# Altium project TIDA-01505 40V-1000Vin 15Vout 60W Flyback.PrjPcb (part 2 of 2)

## Sheet Flyback_PSR.SchDoc: Flyback_without_opto
size 431 x 279 mm; Date: Not shown in title block; ApprovedBy: Not shown in title block; CheckedBy: Not shown in title block; Author: Not shown in title block; CompanyName: Not shown in title block; DrawnBy: X.Gong; Engineer: Not shown in title block; Organization: Not shown in title block; Address1: Not shown in title block; Address2: Not shown in title block; Address3: Not shown in title block; Address4: Not shown in title block; DocumentNumber: 1; Revision: Use project parameter SCH_Rev; SheetNumber: 2; SheetTotal: 4; PageSetup: Record=PageOptions¦CenterHorizontal=True¦CenterVertical=True¦PrintScale=1.00¦XCorrection=1.00¦YCorrection=1.00¦PrintKind=0¦BorderSize=5000000¦LeftOffset=0¦BottomOffset=0¦Orientation=2¦PaperLength=1000¦PaperWidth=1000¦Scale=100¦PaperSource=15¦PrintQuality=600¦MediaType=1¦DitherType=10¦PaperKind=Letter¦PrintScaleMode=1
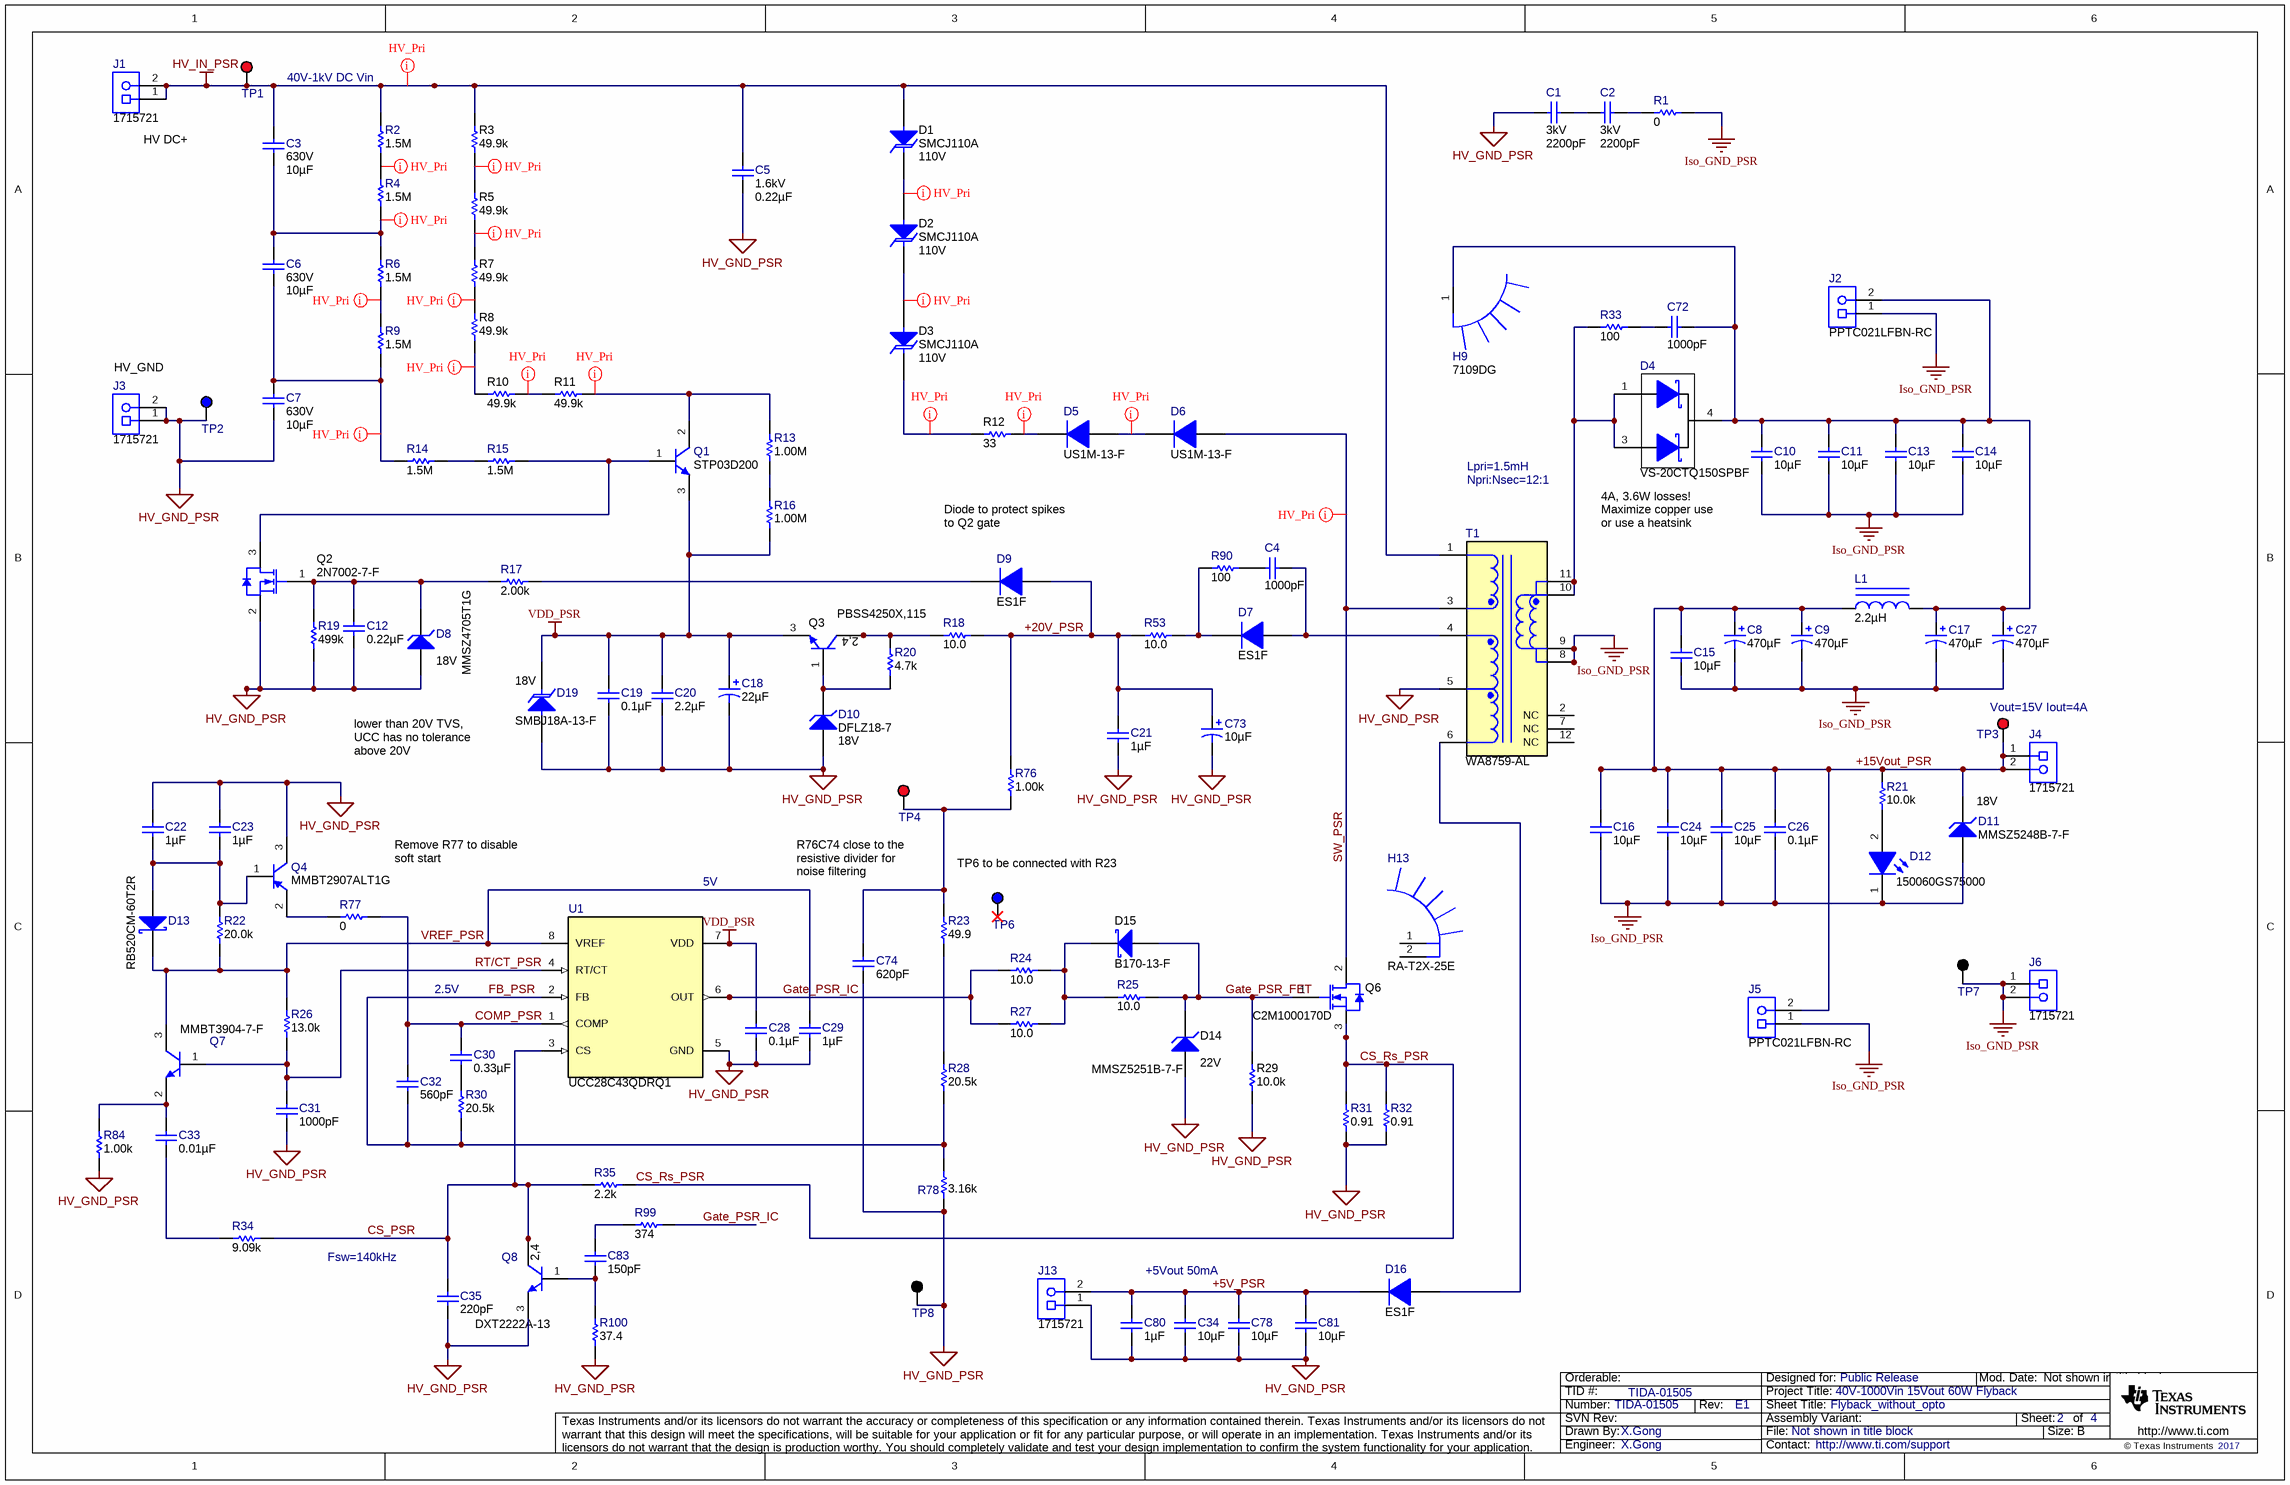
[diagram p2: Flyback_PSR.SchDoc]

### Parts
C1  VDC_V: 3kV  ValueDisplayed: 2200pF  [CK45-RR_1650x600]  (hidden comment: CK45-R3FD222K-NRA)
C2  VDC_V: 3kV  ValueDisplayed: 2200pF  [CK45-RR_1650x600]  (hidden comment: CK45-R3FD222K-NRA)
C3  VDC_V: 630V  ValueDisplayed: 10µF  [B32776P_4200x1800x3250]  (hidden comment: B32776P6106K000)
C4  ValueDisplayed: 1000pF  [1206]  (hidden comment: GRM31B5C2J102JW01L)
C5  VDC_V: 1.6kV  ValueDisplayed: 0.22µF  [Kemet_3200x1800x3300]  (hidden comment: R76TR32204030J)
C6  VDC_V: 630V  ValueDisplayed: 10µF  [B32776P_4200x1800x3250]  (hidden comment: B32776P6106K000)
C7  VDC_V: 630V  ValueDisplayed: 10µF  [B32776P_4200x1800x3250]  (hidden comment: B32776P6106K000)
C8  ValueDisplayed: 470µF  [Chemi-Con_1000x2000]  (hidden comment: EKZE350ELL471MJ20S)
C9  ValueDisplayed: 470µF  [Chemi-Con_1000x2000]  (hidden comment: EKZE350ELL471MJ20S)
C10  ValueDisplayed: 10µF  [0805_HV]  (hidden comment: GRM21BR6YA106KE43L)
C11  ValueDisplayed: 10µF  [0805_HV]  (hidden comment: GRM21BR6YA106KE43L)
C12  ValueDisplayed: 0.22µF  [0805_HV]  (hidden comment: GRM21BR71H224KA01L)
C13  ValueDisplayed: 10µF  [0805_HV]  (hidden comment: GRM21BR6YA106KE43L)
C14  ValueDisplayed: 10µF  [0805_HV]  (hidden comment: GRM21BR6YA106KE43L)
C15  ValueDisplayed: 10µF  [0805_HV]  (hidden comment: GRM21BR6YA106KE43L)
C16  ValueDisplayed: 10µF  [0805_HV]  (hidden comment: GRM21BR6YA106KE43L)
C17  ValueDisplayed: 470µF  [Chemi-Con_1000x2000]  (hidden comment: EKZE350ELL471MJ20S)
C18  ValueDisplayed: 22µF  [SM_RADIAL_D]  (hidden comment: EEE-FK1H220P)
C19  ValueDisplayed: 0.1µF  [0805_HV]  (hidden comment: C2012X7R1H104K085AA)
C20  ValueDisplayed: 2.2µF  [0805_HV]  (hidden comment: CGA4J3X7R1H225K125AB)
C21  ValueDisplayed: 1µF  [1206_180]  (hidden comment: GRM31CR72A105KA01L)
C22  ValueDisplayed: 1µF  [0805_HV]  (hidden comment: GRM21BR71E105KA99L)
C23  ValueDisplayed: 1µF  [0805_HV]  (hidden comment: GRM21BR71E105KA99L)
C24  ValueDisplayed: 10µF  [0805_HV]  (hidden comment: GRM21BR6YA106KE43L)
C25  ValueDisplayed: 10µF  [0805_HV]  (hidden comment: GRM21BR6YA106KE43L)
C26  ValueDisplayed: 0.1µF  [0805_HV]  (hidden comment: C2012X7R1H104K085AA)
C27  ValueDisplayed: 470µF  [Chemi-Con_1000x2000]  (hidden comment: EKZE350ELL471MJ20S)
C28  ValueDisplayed: 0.1µF  [0805_HV]  (hidden comment: C2012X7R1H104K085AA)
C29  ValueDisplayed: 1µF  [0603]  (hidden comment: GRM188R71E105KA12D)
C30  ValueDisplayed: 0.33µF  [0805_HV]  (hidden comment: GRM21BR71E334KA01L)
C31  ValueDisplayed: 1000pF  [0805_HV]  (hidden comment: GCM2165C1H102JA16D)
C32  ValueDisplayed: 560pF  [0805_HV]  (hidden comment: GRM216R71E561KA01D)
C33  ValueDisplayed: 0.01µF  [0805_HV]  (hidden comment: GRM216R71H103KA01D)
C34  ValueDisplayed: 10µF  [0805_HV]  (hidden comment: GRM21BR6YA106KE43L)
C35  ValueDisplayed: 220pF  [0805_HV]  (hidden comment: GRM2165C1H221JA01D)
C72  ValueDisplayed: 1000pF  [1206]  (hidden comment: GRM31B5C2J102JW01L)
C73  ValueDisplayed: 10µF  [SM_RADIAL_E]  (hidden comment: EEE-2AA100UP)
C74  ValueDisplayed: 620pF  [0805_HV]  (hidden comment: GRM2165C2A621JA01D)
C78  ValueDisplayed: 10µF  [0805_HV]  (hidden comment: GRM21BR6YA106KE43L)
C80  ValueDisplayed: 1µF  [1206_180]  (hidden comment: GRM31CR72A105KA01L)
C81  ValueDisplayed: 10µF  [0805_HV]  (hidden comment: GRM21BR6YA106KE43L)
C83  ValueDisplayed: 150pF  [0805_HV]  (hidden comment: GRM2165C1H151JA01D)
D1  SMCJ110A  value 110V  [SMC_265]
D2  SMCJ110A  value 110V  [SMC_265]
D3  SMCJ110A  value 110V  [SMC_265]
D4  VS-20CTQ150SPBF  [DDPAK]
D5  US1M-13-F  [SMA]
D6  US1M-13-F  [SMA]
D7  ES1F  [SMA]
D8  MMSZ4705T1G  value 18V  [SOD-123]
D9  ES1F  [SMA]
D10  DFLZ18-7  value 18V  [PowerDI123]
D11  MMSZ5248B-7-F  value 18V  [SOD-123]
D12  150060GS75000  [WL-SMCW_GREEN]
D13  RB520CM-60T2R  [SOD-923]
D14  MMSZ5251B-7-F  value 22V  [SOD-123]
D15  B170-13-F  [SMA]
D16  ES1F  [SMA]
D19  SMBJ18A-13-F  Vr_V: 18V  [SMB]
H9  7109DG  [Aavid_7109DG]
H13  RA-T2X-25E  [HSINK_RA-T2X-25E]
J1  1715721  [PhoenixContact_1715721]
J2  PPTC021LFBN-RC  [CONN_PPTC021LFBN-RC]
J3  1715721  [PhoenixContact_1715721]
J4  1715721  [PhoenixContact_1715721]
J5  PPTC021LFBN-RC  [CONN_PPTC021LFBN-RC]
J6  1715721  [PhoenixContact_1715721]
J13  1715721  [PhoenixContact_1715721]
L1  ValueDisplayed: 2.2µH  [XAL6030]  (hidden comment: XAL6030-222MEB)
Q1  STP03D200  [TO-220AB]
Q2  2N7002-7-F  [SOT-23]
Q3  PBSS4250X,115  [SOT-89-3]
Q4  MMBT2907ALT1G  [SOT-23]
Q6  C2M1000170D  [TO-247]
Q7  MMBT3904-7-F  [SOT-23]
Q8  DXT2222A-13  [SOT-89-3]
R1  ValueDisplayed: 0  [2010]  (hidden comment: CRCW20100000Z0EF)
R2  ValueDisplayed: 1.5M  [2010]  (hidden comment: ERJ12ZYJ155U)
R3  ValueDisplayed: 49.9k  [2010]  (hidden comment: CRCW201049K9FKEF)
R4  ValueDisplayed: 1.5M  [2010]  (hidden comment: ERJ12ZYJ155U)
R5  ValueDisplayed: 49.9k  [2010]  (hidden comment: CRCW201049K9FKEF)
R6  ValueDisplayed: 1.5M  [2010]  (hidden comment: ERJ12ZYJ155U)
R7  ValueDisplayed: 49.9k  [2010]  (hidden comment: CRCW201049K9FKEF)
R8  ValueDisplayed: 49.9k  [2010]  (hidden comment: CRCW201049K9FKEF)
R9  ValueDisplayed: 1.5M  [2010]  (hidden comment: ERJ12ZYJ155U)
R10  ValueDisplayed: 49.9k  [2010]  (hidden comment: CRCW201049K9FKEF)
R11  ValueDisplayed: 49.9k  [2010]  (hidden comment: CRCW201049K9FKEF)
R12  ValueDisplayed: 33  [2010]  (hidden comment: CRCW201033R0JNEF)
R13  ValueDisplayed: 1.00M  [2010]  (hidden comment: CRCW20101M00FKEF)
R14  ValueDisplayed: 1.5M  [2010]  (hidden comment: ERJ12ZYJ155U)
R15  ValueDisplayed: 1.5M  [2010]  (hidden comment: ERJ12ZYJ155U)
R16  ValueDisplayed: 1.00M  [2010]  (hidden comment: CRCW20101M00FKEF)
R17  ValueDisplayed: 2.00k  [0805_HV]  (hidden comment: CRCW08052K00FKEA)
R18  ValueDisplayed: 10.0  [0805_HV]  (hidden comment: CRCW080510R0FKEA)
R19  ValueDisplayed: 499k  [0603]  (hidden comment: CRCW0603499KFKEA)
R20  ValueDisplayed: 4.7k  [0603]  (hidden comment: CRCW06034K70JNEA)
R21  ValueDisplayed: 10.0k  [0603]  (hidden comment: CRCW060310K0FKEA)
R22  ValueDisplayed: 20.0k  [0805_HV]  (hidden comment: CRCW080520K0FKEA)
R23  ValueDisplayed: 49.9  [0805_HV]  (hidden comment: CRCW080549R9FKEA)
R24  ValueDisplayed: 10.0  [1206]  (hidden comment: CRCW120610R0FKEA)
R25  ValueDisplayed: 10.0  [1206]  (hidden comment: CRCW120610R0FKEA)
R26  ValueDisplayed: 13.0k  [0805_HV]  (hidden comment: CRCW080513K0FKEA)
R27  ValueDisplayed: 10.0  [1206]  (hidden comment: CRCW120610R0FKEA)
R28  ValueDisplayed: 20.5k  [0805_HV]  (hidden comment: CRCW080520K5FKEA)
R29  ValueDisplayed: 10.0k  [1206]  (hidden comment: CRCW120610K0FKEA)
R30  ValueDisplayed: 20.5k  [0805_HV]  (hidden comment: CRCW080520K5FKEA)
R31  ValueDisplayed: 0.91  [2010]  (hidden comment: CRM2010-FX-R910ELF)
R32  ValueDisplayed: 0.91  [2010]  (hidden comment: CRM2010-FX-R910ELF)
R33  ValueDisplayed: 100  [1206]  (hidden comment: CRCW1206100RFKEA)
R34  ValueDisplayed: 9.09k  [0805_HV]  (hidden comment: CRCW08059K09FKEA)
R35  ValueDisplayed: 2.2k  [0805_HV]  (hidden comment: CRCW08052K20JNEA)
R53  ValueDisplayed: 10.0  [1206]  (hidden comment: CRCW120610R0FKEA)
R76  ValueDisplayed: 1.00k  [0805_HV]  (hidden comment: CRCW08051K00FKEA)
R77  ValueDisplayed: 0  [0805_HV]  (hidden comment: CRCW08050000Z0EA)
R78  ValueDisplayed: 3.16k  [0805_HV]  (hidden comment: CRCW08053K16FKEA)
R84  ValueDisplayed: 1.00k  [0805_HV]  (hidden comment: CRCW08051K00FKEA)
R90  ValueDisplayed: 100  [1206]  (hidden comment: CRCW1206100RFKEA)
R99  ValueDisplayed: 374  [0805_HV]  (hidden comment: CRCW0805374RFKEA)
R100  ValueDisplayed: 37.4  [0805_HV]  (hidden comment: CRCW080537R4FKEA)
T1  WA8759-AL  [Coilcraft_WA8537-BL]
TP1  5005  [Keystone5005]  (value not drawn)
TP2  5122  [Keystone5122]  (value not drawn)
TP3  5005  [Keystone5005]  (value not drawn)
TP4  5005  [Keystone5005]  (value not drawn)
TP6  5122  [Keystone5122]  (value not drawn)
TP7  5006  [Keystone5006]  (value not drawn)
TP8  5006  [Keystone5006]  (value not drawn)
U1  UCC28C43QDRQ1  [D0008A_N]

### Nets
HV_GND_PSR: C1.2 C5.2 C7.2 C12.2 C18.2(-) C19.2 C20.2 C21.2 C22.1 C23.1 C28.2 C29.2 C31.2 C34.2 C35.2 C73.2(-) C74.2 C78.2 C80.2 C81.2 D8.2(A) D10.2(A) D14.2(A) D19.2(A) J3.1 J3.2 J13.1 Q2.2(S) Q4.3(C) Q8.3(E) R19.1 R29.1 R31.1 R32.1 R78.1 R84.1 R100.1 T1.5 TP2.1 TP8.1 U1.5(GND)
HV_IN_PSR: C3.1 C5.1 D1.2(A) J1.1 J1.2 R2.2 R3.2 T1.1 TP1.1
Iso_GND_PSR: C8.2(-) C9.2(-) C10.2 C11.2 C13.2 C14.2 C15.2 C16.2 C17.2(-) C24.2 C25.2 C26.2 C27.2(-) D11.2(A) D12.1(K) J2.1 J5.1 J6.1 J6.2 R1.2 T1.8 T1.9 TP7.1
VDD_PSR: C18.1(+) C19.1 C20.1 C28.1 D19.1(K) Q1.3(E) Q3.3(E) R16.1 U1.7(VDD)
+5V_PSR: C34.1 C78.1 C80.1 C81.1 D16.1(K) J13.2
+15Vout_PSR: C8.1(+) C9.1(+) C15.1 C16.1 C24.1 C25.1 C26.1 D11.1(K) J4.1 J4.2 J5.2 L1.1 R21.2 TP3.1
+20V_PSR: C21.1 C73.1(+) D9.2(A) R18.2 R53.1 R76.2
COMP_PSR: C30.1 C32.1 R77.2 U1.1(COMP)
CS_PSR: C35.1 Q8.2(C) Q8.4(C) R34.2 R35.1 U1.3(CS)
CS_Rs_PSR: Q6.3(S) R31.2 R32.2 R35.2
FB_PSR: C32.2 R28.1 R30.1 R78.2 U1.2(FB)
Gate_PSR_FET: D14.1(K) D15.2(A) Q6.1(G) R25.2 R29.2
Gate_PSR_IC: R24.1 R27.1 R99.1 U1.6(OUT)
RT/CT_PSR: C31.1 Q7.1(B) R26.1 U1.4(RT/CT)
SW_PSR: D6.2(A) Q6.2(D) T1.3
VREF_PSR: C29.1 D13.1(K) Q7.3(C) R22.1 R26.2 U1.8(VREF)
NetC1_1: C1.1 C2.2
NetC2_1: C2.1 R1.1
NetC3_2: C3.2 C6.1 R4.1 R6.2
NetC4_1: C4.1 D7.2(A) T1.4
NetC4_2: C4.2 R90.2
NetC6_2: C6.2 C7.1 R9.1 R14.2
NetC10_1: C10.1 C11.1 C13.1 C14.1 C17.1(+) C27.1(+) C72.1 D4.4(K) H9.1 J2.2 L1.2
NetC12_1: C12.1 D8.1(K) Q2.1(G) R17.1 R19.2
NetC22_2: C22.2 C23.2 D13.2(A) Q4.1(B) R22.2
NetC30_2: C30.2 R30.2
NetC33_1: C33.1 Q7.2(E) R84.2
NetC33_2: C33.2 R34.1
NetC72_2: C72.2 R33.2
NetC74_1: C74.1 R23.2 R76.1 TP4.1
NetC83_1: C83.1 R99.2
NetC83_2: C83.2 Q8.1(B) R100.2
NetD1_1: D1.1(K) D2.2(A)
NetD2_1: D2.1(K) D3.2(A)
NetD3_1: D3.1(K) R12.1
NetD4_1: D4.1(A) D4.3(A) R33.1 T1.10 T1.11
NetD5_1: D5.1(K) R12.2
NetD5_2: D5.2(A) D6.1(K)
NetD7_1: D7.1(K) R53.2 R90.1
NetD9_1: D9.1(K) R17.2
NetD10_1: D10.1(K) Q3.1(B) R20.1
NetD12_2: D12.2(A) R21.1
NetD15_1: D15.1(K) R24.2 R25.1 R27.2
NetD16_2: D16.2(A) T1.6
NetQ1_1: Q1.1(B) Q2.3(D) R15.1
NetQ1_2: Q1.2(C) R11.1 R13.2
NetQ3_2: Q3.2(C) Q3.4(C) R18.1 R20.2
NetQ4_2: Q4.2(E) R77.1
NetR2_1: R2.1 R4.2
NetR3_1: R3.1 R5.2
NetR5_1: R5.1 R7.2
NetR6_1: R6.1 R9.2
NetR7_1: R7.1 R8.2
NetR8_1: R8.1 R10.2
NetR10_1: R10.1 R11.2
NetR13_1: R13.1 R16.2
NetR14_1: R14.1 R15.2
NetR23_1: R23.1 R28.2

Not connected (* = marked no-connect by the designer): H13 1 2; T1 2(NC) 7(NC) 12(NC); TP6 1*

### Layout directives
net class 1500V: HV_IN_PSR, NetC3_2, NetC6_2, NetD1_1, NetD2_1, NetD3_1, NetD5_1, NetD5_2, NetQ1_2, NetR2_1, NetR3_1, NetR5_1, NetR6_1, NetR7_1, NetR8_1, NetR10_1, SW_PSR

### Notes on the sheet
- 40V-1kV DC Vin
- (near J1) HV DC+
- (near J3) HV_GND
- Npri:Nsec=12:1
- Lpri=1.5mH
- (near D9) Diode to protect spikes to Q2 gate
- 4A, 3.6W losses! Maximize copper use
  or use a heatsink
- lower than 20V TVS,
  UCC has no tolerance above 20V
- (near TP3) Vout=15V Iout=4A
- (near R77) Remove R77 to disable soft start
- 5V
- R76C74 close to the resistive divider for noise filtering
- TP6 to be connected with R23
- 2.5V
- Fsw=140kHz
- +5Vout 50mA

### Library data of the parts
C1 C2 = CMP-0074791-1: CAP, CERM, 2200 pF, 3000 V,+/- 10%, ?, 16.5x6mm; Manufacturer: TDK; TaMin_C: -25°C; Polarized: N; TempCo: R; SizeAreaWB_mm2: 148.0; U/M: EA; Value: 2200pF; TaMax_C: 125°C; SizeZ_mm: 20.5; SizeX_mm: 16.5; SizeY_mm: 6.0; Value2: 3000V; SizeArea_mm2: 99.0; Cap_F: 2.2nF; AEC Category: Q200
C3 C6 C7 = CMP-0074803-1: CAP, Film, 10 µF, 630 V,+/- 10%, 0.007 ohm, AEC-Q200 Grade 1, TH; Manufacturer: TDK; TaMin_C: -40°C; ESR_ohm: 7m; Polarized: N; SizeAreaWB_mm2: 880.0; U/M: EA; Value: 10uF; TaMax_C: 125°C; SizeZ_mm: 32.5; SizeX_mm: 42.0; SizeY_mm: 18.0; Cap_Case: 42x18x32.5mm; SizeArea_mm2: 756.0; AEC Qualified: Y; IRMS_A: 9.6A; AEC Grade: 1; AEC Category: Q200
C4 C72 = GRM31B5C2J102JW01L: CAP, CERM, 1000 pF, 630 V,+/- 5%, C0G/NP0, 1206; Manufacturer: MuRata; Polarized: N; CompType: Capacitor; Value: 1000pF; U/M: EA; Cap_F: 0.000000001; Tolerance_%: 5; VDC_V: 630; Value2: 630V; TaMin_C: -55; TaMax_C: 125; SizeArea_mm2: 5.12; SizeAreaWB_mm2: 10.92; SizeX_mm: 3.2; SizeY_mm: 1.6; SizeZ_mm: 1.35; AEC Category: Q200; Green_Lifecycle: Not Set; Green_REACh: Incomplete
C5 = CMP-0077096-1: CAP, Film, 0.22 µF, 1600 V,+/- 5%, AEC-Q200 Grade 2, TH; Manufacturer: Kemet; Cap_F: 220nF; SizeAreaWB_mm2: 680.0; SizeArea_mm2: 576.0; AEC Qualified: Y; AEC Category: Q200; Value: 0.22uF; TaMax_C: 105°C; SizeZ_mm: 33.1; AEC Grade: 2; Polarized: N; TaMin_C: -55°C; SizeY_mm: 18.0; Value2: 1600V; U/M: EA; SizeX_mm: 32.0; Cap_Case: 32x18x33mm
C8 C9 C17 C27 = EKZE350ELL471MJ20S: CAP, AL, 470 µF, 35 V, +/- 20%, TH; Manufacturer: Chemi-Con; Polarized: Y; CompType: Capacitor; Value: 470uF; U/M: EA; Cap_F: 0.00047; Tolerance_%: 20; VDC_V: 35; Value2: 35V; IRMS_A: 1.82; TaMin_C: -40; TaMax_C: 105; Cap_Case: 10x20; SizeAreaWB_mm2: 144; SizeArea_mm2: 100; SizeX_mm: 10; SizeZ_mm: 21.5; AEC Category: Q200; AEC Qualified: N
C10 C11 C13-C16 C24 C25 C34 C78 C81 = GRM21BR6YA106KE43L: CAP, CERM, 10 µF, 35 V,+/- 10%, X5R, 0805; Manufacturer: MuRata; Polarized: N; CompType: Capacitor; Value: 10uF; U/M: EA; Cap_F: 0.00001; Tolerance_%: 10; VDC_V: 35; Value2: 35V; TaMin_C: -55; TaMax_C: 85; Cap_Case: 0805; SizeArea_mm2: 2.5; SizeAreaWB_mm2: 6.75; SizeX_mm: 2; SizeY_mm: 1.25; SizeZ_mm: 1.45; AEC Category: Q200; Green_Lifecycle: Active; Green_REACh: Passed
C12 = GRM21BR71H224KA01L: CAP, CERM, 0.22 µF, 50 V,+/- 10%, X7R, 0805; Manufacturer: MuRata; Polarized: N; CompType: Capacitor; Value: 0.22uF; U/M: EA; Cap_F: 0.00000022; Tolerance_%: 10; VDC_V: 50; Value2: 50V; TaMin_C: -55; TaMax_C: 125; Cap_Case: 0805; SizeArea_mm2: 2.5; SizeAreaWB_mm2: 6.75; SizeX_mm: 2; SizeY_mm: 1.25; SizeZ_mm: 1.45; AEC Category: Q200; Green_Lifecycle: Active; Green_REACh: Passed
C18 = EEE-FK1H220P: CAP, AL, 22 µF, 50 V, +/- 20%, 0.88 ohm, AEC-Q200 Grade 2, SMD; Manufacturer: Panasonic; Polarized: Y; CompType: Capacitor; Value: 22uF; U/M: EA; Cap_F: 0.000022; Tolerance_%: 20; VDC_V: 50; Value2: 50V; ESR_ohm: 0.88; IRMS_A: 0.165; TaMin_C: -55; TaMax_C: 105; Cap_Case: D; SizeAreaWB_mm2: 84.28; SizeArea_mm2: 51.48; SizeX_mm: 7.8; SizeY_mm: 6.6; SizeZ_mm: 5.4; AEC Category: Q200; AEC Grade: 2; Green_Lifecycle: Active; Green_REACh: Passed
C19 C26 C28 = C2012X7R1H104K085AA: CAP, CERM, 0.1 µF, 50 V,+/- 10%, X7R, 0805; Manufacturer: TDK; Polarized: N; CompType: Capacitor; Value: 0.1uF; U/M: EA; Cap_F: 0.0000001; Tolerance_%: 10; ESR_ohm: 0.02619; Value1: 0.02619 ohm; VDC_V: 50; Value2: 50V; IRMS_A: 1.29514; TaMin_C: -55; TaMax_C: 125; Cap_Case: 0805; SizeArea_mm2: 2.5; SizeAreaWB_mm2: 6.75; SizeX_mm: 2; SizeY_mm: 1.25; SizeZ_mm: 1.45; AEC Category: Q200; Green_Lifecycle: NRND; Green_REACh: Passed
C20 = CGA4J3X7R1H225K125AB: CAP, CERM, 2.2 µF, 50 V,+/- 10%, X7R, AEC-Q200 Grade 1, 0805; Manufacturer: TDK; Polarized: N; CompType: Capacitor; Value: 2.2uF; U/M: EA; Cap_F: 0.0000022; Tolerance_%: 10; ESR_ohm: 0.003288; Value1: 0.003288 ohm; VDC_V: 50; Value2: 50V; IRMS_A: 3.60029; TaMin_C: -55; TaMax_C: 125; Cap_Case: 0805; SizeArea_mm2: 2.5; SizeAreaWB_mm2: 6.75; SizeX_mm: 2; SizeY_mm: 1.25; SizeZ_mm: 1.45; AEC Category: Q200; AEC Qualified: Y; AEC Grade: 1
C21 C80 = GRM31CR72A105KA01L: CAP, CERM, 1 µF, 100 V,+/- 10%, X7R, 1206; Manufacturer: MuRata; Polarized: N; CompType: Capacitor; Value: 1uF; U/M: EA; Cap_F: 0.000001; Tolerance_%: 10; VDC_V: 100; Value2: 100V; TaMin_C: -55; TaMax_C: 125; Cap_Case: 1206; SizeArea_mm2: 5.12; SizeAreaWB_mm2: 10.92; SizeX_mm: 3.2; SizeY_mm: 1.6; SizeZ_mm: 1.8; AEC Category: Q200; Green_Lifecycle: Active; Green_REACh: Passed
C22 C23 = GRM21BR71E105KA99L: CAP, CERM, 1 µF, 25 V,+/- 10%, X7R, 0805; Manufacturer: MuRata; Polarized: N; CompType: Capacitor; Value: 1uF; U/M: EA; Cap_F: 0.000001; Tolerance_%: 10; VDC_V: 25; Value2: 25V; TaMin_C: -55; TaMax_C: 125; Cap_Case: 0805; SizeArea_mm2: 2.5; SizeAreaWB_mm2: 6.75; SizeX_mm: 2; SizeY_mm: 1.25; SizeZ_mm: 1.45; AEC Category: Q200; Green_Lifecycle: Active; Green_REACh: Passed
C29 = GRM188R71E105KA12D: CAP, CERM, 1 µF, 25 V,+/- 10%, X7R, 0603; Manufacturer: MuRata; Polarized: N; CompType: Capacitor; Value: 1uF; U/M: EA; Cap_F: 0.000001; Tolerance_%: 10; VDC_V: 25; Value2: 25V; TaMin_C: -55; TaMax_C: 125; SizeArea_mm2: 1.28; SizeAreaWB_mm2: 4.68; SizeX_mm: 1.6; SizeY_mm: 0.8; SizeZ_mm: 1; AEC Category: Q200; Green_Lifecycle: Active; Green_REACh: Passed
C30 = GRM21BR71E334KA01L: CAP, CERM, 0.33 µF, 25 V,+/- 10%, X7R, 0805; Manufacturer: MuRata; Polarized: N; CompType: Capacitor; Value: 0.33uF; U/M: EA; Cap_F: 0.00000033; Tolerance_%: 10; VDC_V: 25; Value2: 25V; TaMin_C: -55; TaMax_C: 125; Cap_Case: 0805; SizeArea_mm2: 2.5; SizeAreaWB_mm2: 6.75; SizeX_mm: 2; SizeY_mm: 1.25; SizeZ_mm: 1.45; AEC Category: Q200
C31 = GCM2165C1H102JA16D: CAP, CERM, 1000 pF, 50 V,+/- 5%, C0G/NP0, AEC-Q200 Grade 1, 0805; Manufacturer: MuRata; Polarized: N; CompType: Capacitor; Value: 1000pF; U/M: EA; Cap_F: 0.000000001; Tolerance_%: 5; VDC_V: 50; Value2: 50V; TaMin_C: -55; TaMax_C: 125; Cap_Case: 0805; SizeArea_mm2: 2.5; SizeAreaWB_mm2: 6.75; SizeX_mm: 2; SizeY_mm: 1.25; SizeZ_mm: 1.45; AEC Category: Q200; AEC Qualified: Y; AEC Grade: 1
C32 = GRM216R71E561KA01D: CAP, CERM, 560 pF, 25 V,+/- 10%, X7R, 0805; Manufacturer: MuRata; Polarized: N; CompType: Capacitor; Value: 560pF; U/M: EA; Cap_F: 0.00000000056; Tolerance_%: 10; VDC_V: 25; Value2: 25V; TaMin_C: -55; TaMax_C: 125; Cap_Case: 0805; SizeArea_mm2: 2.5; SizeAreaWB_mm2: 6.75; SizeX_mm: 2; SizeY_mm: 1.25; SizeZ_mm: 1.45; AEC Category: Q200
C33 = GRM216R71H103KA01D: CAP, CERM, 0.01 µF, 50 V,+/- 10%, X7R, 0805; Manufacturer: MuRata; Polarized: N; CompType: Capacitor; Value: 0.01uF; U/M: EA; Cap_F: 0.00000001; Tolerance_%: 10; VDC_V: 50; Value2: 50V; TaMin_C: -55; TaMax_C: 125; Cap_Case: 0805; SizeArea_mm2: 2.5; SizeAreaWB_mm2: 6.75; SizeX_mm: 2; SizeY_mm: 1.25; SizeZ_mm: 1.45; AEC Category: Q200; Green_Lifecycle: Active; Green_REACh: Passed
C35 = GRM2165C1H221JA01D: CAP, CERM, 220 pF, 50 V,+/- 5%, C0G/NP0, 0805; Manufacturer: MuRata; Polarized: N; CompType: Capacitor; Value: 220pF; U/M: EA; Cap_F: 0.00000000022; Tolerance_%: 5; VDC_V: 50; Value2: 50V; TaMin_C: -55; TaMax_C: 125; Cap_Case: 0805; SizeArea_mm2: 2.5; SizeAreaWB_mm2: 6.75; SizeX_mm: 2; SizeY_mm: 1.25; SizeZ_mm: 1.45; AEC Category: Q200
C73 = EEE-2AA100UP: CAP, AL, 10 µF, 100 V, +/- 20%, AEC-Q200 Grade 3, SMD; Manufacturer: Panasonic; Polarized: Y; CompType: Capacitor; Value: 10uF; U/M: EA; Cap_F: 0.00001; Tolerance_%: 20; VDC_V: 100; Value2: 100V; IRMS_A: 0.05; TaMin_C: -40; TaMax_C: 85; Cap_Case: 8.0x6.0mm; SizeAreaWB_mm2: 118.45; SizeArea_mm2: 78.85; SizeX_mm: 9.5; SizeY_mm: 8.3; SizeZ_mm: 6.2; AEC Category: Q200; AEC Grade: 3
C74 = GRM2165C2A621JA01D: CAP, CERM, 620 pF, 100 V,+/- 5%, C0G/NP0, 0805; Manufacturer: MuRata; Polarized: N; CompType: Capacitor; Value: 620pF; U/M: EA; Cap_F: 0.00000000062; Tolerance_%: 5; VDC_V: 100; Value2: 100V; TaMin_C: -55; TaMax_C: 125; Cap_Case: 0805; SizeArea_mm2: 2.5; SizeAreaWB_mm2: 6.75; SizeX_mm: 2; SizeY_mm: 1.25; SizeZ_mm: 1.45; AEC Category: Q200
C83 = GRM2165C1H151JA01D: CAP, CERM, 150 pF, 50 V,+/- 5%, C0G/NP0, 0805; Manufacturer: MuRata; Polarized: N; CompType: Capacitor; Value: 150pF; U/M: EA; Cap_F: 0.00000000015; Tolerance_%: 5; VDC_V: 50; Value2: 50V; TaMin_C: -55; TaMax_C: 125; Cap_Case: 0805; SizeArea_mm2: 2.5; SizeAreaWB_mm2: 6.75; SizeX_mm: 2; SizeY_mm: 1.25; SizeZ_mm: 1.45; AEC Category: Q200
D1-D3 = SMCJ110A: Diode, TVS, Uni, 110 V, SMC; Manufacturer: Littelfuse; U/M: EA; Power_W: 6.5; Vr_V: 110; Value1: 6.5W; RJA_CperW: 75; SizeAreaWB_mm2: 78.5757; SizeArea_mm2: 46.8857; SizeX_mm: 7.94; SizeY_mm: 5.905; SizeZ_mm: 2.62; AEC Category: Q101
D4 = VS-20CTQ150SPBF: Diode, Schottky, 150 V, 10 A, DDPAK; Manufacturer: Vishay-Semiconductor; U/M: EA; Vf_V: 0.66; Value: 150V; Value1: 10A; Value2: 0.66V; Io_A: 10; Vr_V: 150; TJmax_C: 175; SizeAreaWB_mm2: 209.6992; SizeArea_mm2: 154.8892; SizeX_mm: 15.245; SizeY_mm: 10.16; SizeZ_mm: 4.445; AEC Category: Q101; Green_Lifecycle: Not Set; Green_REACh: Incomplete
D5 D6 = US1M-13-F: Diode, Ultrafast, 1000 V, 1 A, SMA; Manufacturer: Diodes Inc.; U/M: EA; Vf_V: 1.7; Value: 1000V; Value1: 1A; Value2: 1.7V; Io_A: 1; Vr_V: 1000; TJmax_C: 150; RJC_CperW: 30; SizeAreaWB_mm2: 37.3428; SizeArea_mm2: 16.3228; SizeX_mm: 5.59; SizeY_mm: 2.92; SizeZ_mm: 2.87; AEC Category: Q101; Green_Lifecycle: Not Set; Green_REACh: Incomplete
D7 D9 D16 = CMP-0074851-1: Diode, Fast Rectifier, 300 V, 1 A, SMA; Manufacturer: Fairchild Semiconductor; Io_A: 1A; Green_Lifecycle: Active; SizeAreaWB_mm2: 37.3428; Vr_V: 300V; Green_REACh: Passed; TJmax_C: 150°C; U/M: EA; Value: 300V; SizeZ_mm: 2.87; SizeX_mm: 5.59; SizeY_mm: 2.92; Vf_V: 1.3V; SizeArea_mm2: 16.3228; AEC Qualified: N; AEC Category: Q101; RJC_CperW: 35.0
D8 = MMSZ4705T1G: Diode, Zener, 18 V, 500 mW, SOD-123; Manufacturer: ON Semiconductor; SymbolCreator: a0412235; U/M: EA; Power_W: 0.5; Vz_V: 18; Value1: 0.5W; RJA_CperW: 340; SizeAreaWB_mm2: 13.095; SizeArea_mm2: 6.545; SizeX_mm: 3.85; SizeY_mm: 1.7; SizeZ_mm: 1.35; AEC Category: Q101
D10 = DFLZ18-7: Diode, Zener, 18 V, 1 W, PowerDI123; Manufacturer: Diodes Inc.; SymbolCreator: a0412235; U/M: EA; Power_W: 1; Vz_V: 18; Value1: 1W; RJA_CperW: 110; SizeAreaWB_mm2: 13.066; SizeArea_mm2: 6.586; SizeX_mm: 3.7; SizeY_mm: 1.78; SizeZ_mm: 0.98; AEC Category: Q101
D11 = CMP-0005755-2: Diode, Zener, 18 V, 500 mW, SOD-123; Manufacturer: Diodes Inc.; Power_W: 500mW; SizeAreaWB_mm2: 13.095; Value1: 0.5W; RJA_CperW: 350; U/M: EA; SizeZ_mm: 1.35; SizeX_mm: 3.85; SizeY_mm: 1.7; SizeArea_mm2: 6.545; AEC Category: Q101
D12 = CMP-0002905-1: LED, Green, SMD; Manufacturer: Wurth Elektronik; Io_A: 20mA; Tjmax_C: 85°C; Value1: W; U/M: EA; Angle: 140; Vf_V: 3.2V; Type: InGaN
D13 = RB520CM-60T2R: Diode, Schottky, 60 V, 0.1 A, SOD-923; Manufacturer: Rohm; U/M: EA; Value: 60V; Value1: 0.1A; Io_A: 0.1; Vr_V: 60; TJmax_C: 150; SizeAreaWB_mm2: 3.2; SizeArea_mm2: 0.6; SizeX_mm: 1; SizeZ_mm: 0.4; AEC Category: Q101; AEC Qualified: N
D14 = MMSZ5251B-7-F: Diode, Zener, 22 V, 500 mW, SOD-123; Manufacturer: Diodes Inc.; SymbolCreator: a0412235; U/M: EA; Power_W: 0.5; Vz_V: 22; Value1: 0.5W; RJA_CperW: 350; SizeAreaWB_mm2: 13.095; SizeArea_mm2: 6.545; SizeX_mm: 3.85; SizeY_mm: 1.7; SizeZ_mm: 1.35; AEC Category: Q101
D15 = B170-13-F: Diode, Schottky, 70 V, 1 A, SMA; Manufacturer: Diodes Inc.; U/M: EA; Vf_V: 0.79; Value: 70V; Value1: 1A; Value2: 0.79V; Io_A: 1; Vr_V: 70; TJmax_C: 150; RJC_CperW: 25; SizeAreaWB_mm2: 37.3428; SizeArea_mm2: 16.3228; SizeX_mm: 5.59; SizeY_mm: 2.92; SizeZ_mm: 2.87; AEC Category: Q101; Green_Lifecycle: Active; Green_REACh: Passed
D19 = CMP-0005551-2: Diode, TVS, Uni, 18 V, 29.2 Vc, SMB; Manufacturer: Diodes Inc.; Power_W: 5W; SizeAreaWB_mm2: 44.156; U/M: EA; Value: 18V; SizeZ_mm: 2.6; SizeX_mm: 5.6; SizeY_mm: 3.81; SizeArea_mm2: 21.336; AEC Category: Q101
H9 = CMP-0004038-1: Surface mount heat sink for D2PAK; Manufacturer: Aavid
H13 = CMP-0076741-1: Heatsink, TO-220, TO-218, TO-247; Manufacturer: Ohmite
J1 J3 J4 J6 J13 = CMP-0055471-1: Terminal Block, 5.08 mm, 2x1, TH; Manufacturer: Phoenix Contact; Cert_VDE: Y; CNHeader: FALSE; Current_A: 17.5A; Green_Lifecycle: Not Set; Gender: Female; Cert_CULUS: N; Green_REACh: Incomplete; Voltage_V: 400V; Row_Count: 1; Pitch_mm: 5.08; ContactFinish: Tin; CT: TRUE
J2 J5 = CMP-0054631-1: Receptacle, 100mil, 2x1, Tin, TH; Manufacturer: Sullins Connector Solutions; CNHeader: FALSE; Current_A: 3A; Gender: Female; Voltage_V: 250V; CompType: Socket Strip; Pitch_mm: 2.54; CT: TRUE; Cert_UL: Y
L1 = XAL6030-222MEB: Inductor, Shielded, Composite, 2.2 µH, 12.7 A, 0.012 ohm, SMD; Manufacturer: Coilcraft; Value: 2.2uH; Ind_H: 2.2E-6; Imax_A: 12.7; Irms: 12.7A @ 40C rise; Isat: 15.9A @ 30% inductance drop; DCR_ohm: 0.012; Value2: 12.7A; SizeAreaWB_mm2: 71.5616; SizeArea_mm2: 41.7216; SizeX_mm: 6.36; SizeY_mm: 6.56; SizeZ_mm: 3.1; AEC Category: Q200; Green_Lifecycle: Not Set; Green_REACh: Incomplete
Q1 = CMP-0074796-1: Transistor, NPN, 1200 V, .1 A, TO-220AB; Manufacturer: STMicroelectronics; TaMin_C: -65°C; SizeAreaWB_mm2: 79.3; Value1: .1 A; Vceo_V: 1.2kV; U/M: EA; Value: 1200 V; TaMax_C: 150°C; IcRated_A: 1dA; SizeZ_mm: 19.4; SizeX_mm: 10.2; SizeY_mm: 4.5; SizeArea_mm2: 45.9; CompType: BJT; PNP: 0.0; AEC Qualified: N; NPN: 1.0; Vcesat1_V: 2V; AEC Category: Q101
Q2 = 2N7002-7-F: MOSFET, N-CH, 60 V, 0.17 A, SOT-23; Manufacturer: Diodes Inc.; Alternate Manufacturer: None; U/M: EA; ChType: N; Value: 60V; VdsMax_V: 60; Value1: 7.5 ohm; Rdson45_ohm: 7.5; Value2: 223 nC; QgTyp_nC: 223; Vgs_V: 20; IdsMax_A: 0.17; SizeAreaWB_mm2: 14; SizeX_mm: 2.5; SizeY_mm: 3; SizeZ_mm: 1.1; AEC Category: Q101; Green_Lifecycle: Active; Green_REACh: Passed
Q3 = PBSS4250X,115, Nexperia: Transistor, NPN, 50 V, 2 A, SOT-89; SymbolCreator: a0412235; PNP: 0; NPN: 1; Vceo_V: 50; Vcesat1_V: 0.25; Value: 50 V; IcRated_A: 2; Value1: 2 A; TaMin_C: -65; TaMax_C: 150; SizeAreaWB_mm2: 28.05; SizeArea_mm2: 18.45; SizeX_mm: 4.1; SizeY_mm: 4.5; SizeZ_mm: 1.5; CompType: BJT; U/M: EA; AEC Category: Q101; AEC Qualified: N
Q4 = MMBT2907ALT1G, ON Semiconductor: Transistor, PNP, 60 V, 0.6 A, SOT-23; CompType: BJT; PNP: 1; NPN: 0; Vceo_V: 60; Vcesat1_V: 1.6; Value: 60 V; IcRated_A: 0.6; Value1: 0.6 A; TaMin_C: -55; TaMax_C: 150; SizeAreaWB_mm2: 14; SizeArea_mm2: 7.5; SizeX_mm: 2.5; SizeY_mm: 3; SizeZ_mm: 1.1; U/M: EA; AEC Category: Q101; Green_Lifecycle: Active; Green_REACh: Passed
Q6 = C2M1000170D: MOSFET, N-CH, 1700 V, 5 A, TO-247; Manufacturer: Cree; Alternate Manufacturer: None; U/M: EA; ChType: N; Value: 1700V; VdsMax_V: 1700; Value1: ? ohm; Value2: 13 nC; QgTyp_nC: 13; Vgs_V: 25; IdsMax_A: 5; SizeAreaWB_mm2: 123.2; SizeArea_mm2: 78; SizeX_mm: 15.6; AEC Category: Q101; Green_Lifecycle: Not Set; Green_REACh: Incomplete
Q7 = MMBT3904-7-F, Diodes Inc.: Transistor, NPN, 40 V, 0.2 A, SOT-23; CompType: BJT; PNP: 0; NPN: 1; Vceo_V: 40; Vcesat1_V: 0.2; Value: 40 V; Value1: 0.2 A; HfeMax: 400; TaMin_C: -55; TaMax_C: 150; SizeAreaWB_mm2: 14; SizeArea_mm2: 7.5; SizeX_mm: 2.5; SizeY_mm: 3; SizeZ_mm: 1.1; U/M: EA; AEC Category: Q101; Green_Lifecycle: Active; Green_REACh: Passed
Q8 = DXT2222A-13, Diodes Inc.: Transistor, NPN, 40 V, 0.6 A, SOT-89; SymbolCreator: a0412235; PNP: 0; NPN: 1; Vceo_V: 40; Value: 40 V; IcRated_A: 0.6; Value1: 0.6 A; HfeMax: 300; TaMin_C: -55; TaMax_C: 150; SizeAreaWB_mm2: 28.05; SizeArea_mm2: 18.45; SizeX_mm: 4.1; SizeY_mm: 4.5; SizeZ_mm: 1.5; CompType: BJT; U/M: EA; AEC Category: Q101; Green_Lifecycle: Active; Green_REACh: Passed
R1 = CMP-0016044-2: RES, 0, 5%, 0.75 W, AEC-Q200 Grade 0, 2010; Manufacturer: Vishay-Dale; Power_W: 750mW; TempCo: ppm/C; Value_Code: 0000; U/M: EA; Value: 0; EIA_Code: E24; SizeX_mm: 5; SizeY_mm: 2.5; SizeZ_mm: 1.66; Value2: 0.75W; SizeArea_mm2: 12.5; AEC Qualified: Y; AEC Category: Q200
R2 = CMP-0077778-1: RES, 1.5 M, 5%, 0.75 W, AEC-Q200 Grade 0, 2010; Manufacturer: Panasonic; Power_W: 750mW; Value_Code: 1M50; U/M: EA; Value: 1.5Meg; EIA_Code: E24; SizeX_mm: 5.0; SizeY_mm: 2.5; SizeZ_mm: 1.66; Value2: 0.75W; SizeArea_mm2: 12.5; AEC Qualified: Y; VDC_V: 200V; AEC Grade: 0; AEC Category: Q200
R3 R5 R7 R8 R10 R11 = CRCW201049K9FKEF: RES, 49.9 k, 1%, 0.75 W, AEC-Q200 Grade 0, 2010; Manufacturer: Vishay-Dale; CompType: Resistor; Value: 49.9k; Res_ohm: 49900; Value_Code: 49k9; Tolerance_%: 1; Power_W: 0.75; Value2: 0.75W; VDC_V: 400; TempCo: 100 ppm/C; SizeArea_mm2: 12.5; SizeX_mm: 5; SizeY_mm: 2.5; SizeZ_mm: 1.66; EIA_Code: E96; U/M: EA; AEC Category: Q200; AEC Qualified: Y; AEC Grade: 0
R4 R6 R9 R14 R15 = CMP-0077778-1: RES, 1.5 M, 5%, 0.75 W, AEC-Q200 Grade 0, 2010; Manufacturer: Panasonic; Power_W: 750mW; Value_Code: 1M50; U/M: EA; Value: 1.5Meg; EIA_Code: E24; SizeX_mm: 5.0; SizeY_mm: 2.5; SizeZ_mm: 1.66; Value2: 0.75W; SizeArea_mm2: 12.5; CompType: Resistor; AEC Qualified: Y; VDC_V: 200V; AEC Grade: 0; AEC Category: Q200
R12 = CRCW201033R0JNEF: RES, 33, 5%, 0.75 W, AEC-Q200 Grade 0, 2010; Manufacturer: Vishay-Dale; CompType: Resistor; Value: 33; Value_Code: 33R0; Tolerance_%: 5; Power_W: 0.75; Value2: 0.75W; VDC_V: 400; TempCo: 200 ppm/C; SizeArea_mm2: 12.5; SizeY_mm: 2.5; SizeZ_mm: 1.66; EIA_Code: E24; U/M: EA; AEC Category: Q200; AEC Qualified: Y; AEC Grade: 0
R13 R16 = CRCW20101M00FKEF: RES, 1.00 M, 1%, 0.75 W, AEC-Q200 Grade 0, 2010; Manufacturer: Vishay-Dale; CompType: Resistor; Value: 1.00Meg; Res_ohm: 1000000; Value_Code: 1M00; Tolerance_%: 1; Power_W: 0.75; Value2: 0.75W; VDC_V: 400; TempCo: 100 ppm/C; SizeArea_mm2: 12.5; SizeX_mm: 5; SizeY_mm: 2.5; SizeZ_mm: 1.66; EIA_Code: E96; U/M: EA; AEC Category: Q200; AEC Qualified: Y; AEC Grade: 0
R17 = CRCW08052K00FKEA: RES, 2.00 k, 1%, 0.125 W, 0805; Manufacturer: Vishay-Dale; CompType: Resistor; Value: 2.00k; Res_ohm: 2000; Value_Code: 2k00; Tolerance_%: 1; Power_W: 0.125; Value2: 0.125W; VDC_V: 150; TempCo: 100 ppm/C; SizeArea_mm2: 2.5; SizeX_mm: 2; SizeY_mm: 1.25; SizeZ_mm: 1.45; EIA_Code: E96; U/M: EA; AEC Category: Q200; Green_Lifecycle: Active; Green_REACh: Passed
R18 = CRCW080510R0FKEA: RES, 10.0, 1%, 0.125 W, 0805; Manufacturer: Vishay-Dale; CompType: Resistor; Value: 10.0; Res_ohm: 10; Value_Code: 10R0; Tolerance_%: 1; Power_W: 0.125; Value2: 0.125W; VDC_V: 150; TempCo: 100 ppm/C; SizeArea_mm2: 2.5; SizeX_mm: 2; SizeY_mm: 1.25; SizeZ_mm: 1.45; EIA_Code: E96; U/M: EA; AEC Category: Q200; Green_Lifecycle: Active; Green_REACh: Passed
R19 = CRCW0603499KFKEA: RES, 499 k, 1%, 0.1 W, 0603; Manufacturer: Vishay-Dale; CompType: Resistor; Value: 499k; Res_ohm: 499000; Tolerance_%: 1; Power_W: 0.1; Value2: 0.1W; VDC_V: 75; TempCo: 100 ppm/C; SizeArea_mm2: 1.28; SizeX_mm: 1.6; SizeY_mm: 0.8; EIA_Code: E96; U/M: EA; AEC Category: Q200; Green_Lifecycle: Active; Green_REACh: Passed
R20 = CRCW06034K70JNEA: RES, 4.7 k, 5%, 0.1 W, 0603; Manufacturer: Vishay-Dale; CompType: Resistor; Value: 4.7k; Res_ohm: 4700; Value_Code: 4k70; Tolerance_%: 5; Power_W: 0.1; Value2: 0.1W; VDC_V: 75; TempCo: 200 ppm/C; SizeArea_mm2: 1.28; SizeX_mm: 1.6; SizeY_mm: 0.8; SizeZ_mm: 1; EIA_Code: E24; U/M: EA; AEC Category: Q200; Green_Lifecycle: Active; Green_REACh: Passed
R21 = CMP-0021998-2: RES, 10.0 k, 1%, 0.1 W, 0603; Manufacturer: Vishay-Dale; Power_W: 100mW; TempCo: 100 ppm/C; Value_Code: 10k0; U/M: EA; Value: 10.0k; EIA_Code: E96; Res_ohm: 10k; SizeX_mm: 1.6; SizeY_mm: 0.8; SizeZ_mm: 1; Value2: 0.1W; SizeArea_mm2: 1.28; VDC_V: 75V; AEC Category: Q200
R22 = CRCW080520K0FKEA: RES, 20.0 k, 1%, 0.125 W, 0805; Manufacturer: Vishay-Dale; CompType: Resistor; Value: 20.0k; Res_ohm: 20000; Value_Code: 20k0; Tolerance_%: 1; Power_W: 0.125; Value2: 0.125W; VDC_V: 150; TempCo: 100 ppm/C; SizeArea_mm2: 2.5; SizeX_mm: 2; SizeY_mm: 1.25; SizeZ_mm: 1.45; EIA_Code: E96; U/M: EA; AEC Category: Q200; Green_Lifecycle: Active; Green_REACh: Passed
R23 = CRCW080549R9FKEA: RES, 49.9, 1%, 0.125 W, 0805; Manufacturer: Vishay-Dale; CompType: Resistor; Value: 49.9; Value_Code: 49R9; Tolerance_%: 1; Power_W: 0.125; Value2: 0.125W; VDC_V: 150; TempCo: 100 ppm/C; SizeArea_mm2: 2.5; SizeX_mm: 2; SizeY_mm: 1.25; SizeZ_mm: 1.45; EIA_Code: E96; U/M: EA; AEC Category: Q200; Green_Lifecycle: Active; Green_REACh: Passed
R24 R25 R27 R53 = CRCW120610R0FKEA: RES, 10.0, 1%, 0.25 W, 1206; Manufacturer: Vishay-Dale; CompType: Resistor; Value: 10.0; Res_ohm: 10; Value_Code: 10R0; Tolerance_%: 1; Power_W: 0.25; Value2: 0.25W; VDC_V: 200; TempCo: 100 ppm/C; SizeArea_mm2: 5.12; SizeX_mm: 3.2; SizeY_mm: 1.6; SizeZ_mm: 1.35; EIA_Code: E96; U/M: EA; AEC Category: Q200; Green_Lifecycle: Active; Green_REACh: Passed
R26 = CRCW080513K0FKEA: RES, 13.0 k, 1%, 0.125 W, 0805; Manufacturer: Vishay-Dale; CompType: Resistor; Value: 13.0k; Res_ohm: 13000; Value_Code: 13k0; Tolerance_%: 1; Power_W: 0.125; Value2: 0.125W; VDC_V: 150; TempCo: 100 ppm/C; SizeArea_mm2: 2.5; SizeX_mm: 2; SizeY_mm: 1.25; SizeZ_mm: 1.45; EIA_Code: E96; U/M: EA; AEC Category: Q200
R28 R30 = CRCW080520K5FKEA: RES, 20.5 k, 1%, 0.125 W, 0805; Manufacturer: Vishay-Dale; CompType: Resistor; Value: 20.5k; Res_ohm: 20500; Value_Code: 20k5; Tolerance_%: 1; Power_W: 0.125; Value2: 0.125W; VDC_V: 150; TempCo: 100 ppm/C; SizeArea_mm2: 2.5; SizeX_mm: 2; SizeY_mm: 1.25; SizeZ_mm: 1.45; EIA_Code: E96; U/M: EA; AEC Category: Q200; Green_Lifecycle: Active; Green_REACh: Passed
R29 = CRCW120610K0FKEA: RES, 10.0 k, 1%, 0.25 W, 1206; Manufacturer: Vishay-Dale; CompType: Resistor; Value: 10.0k; Res_ohm: 10000; Value_Code: 10k0; Tolerance_%: 1; Power_W: 0.25; Value2: 0.25W; VDC_V: 200; TempCo: 100 ppm/C; SizeArea_mm2: 5.12; SizeX_mm: 3.2; SizeY_mm: 1.6; SizeZ_mm: 1.35; EIA_Code: E96; U/M: EA; AEC Category: Q200; Green_Lifecycle: Active; Green_REACh: Passed
R31 R32 = CRM2010-FX-R910ELF: RES, 0.91, 1%, 1 W, 2010; Manufacturer: Bourns; CompType: Resistor; Value: 0.91; Value_Code: R910; Tolerance_%: 1; Value2: 1W; TempCo: 100 ppm/C; SizeArea_mm2: 12.5; SizeX_mm: 5; SizeY_mm: 2.5; SizeZ_mm: 1.66; EIA_Code: E96; U/M: EA; AEC Category: Q200
R33 R90 = CRCW1206100RFKEA: RES, 100, 1%, 0.25 W, 1206; Manufacturer: Vishay-Dale; CompType: Resistor; Value: 100; Value_Code: 100R; Tolerance_%: 1; Power_W: 0.25; Value2: 0.25W; VDC_V: 200; TempCo: 100 ppm/C; SizeArea_mm2: 5.12; SizeX_mm: 3.2; SizeY_mm: 1.6; SizeZ_mm: 1.35; EIA_Code: E96; U/M: EA; AEC Category: Q200; Green_Lifecycle: Active; Green_REACh: Passed
R34 = CRCW08059K09FKEA: RES, 9.09 k, 1%, 0.125 W, 0805; Manufacturer: Vishay-Dale; CompType: Resistor; Value: 9.09k; Res_ohm: 9090; Value_Code: 9k09; Tolerance_%: 1; Power_W: 0.125; Value2: 0.125W; VDC_V: 150; TempCo: 100 ppm/C; SizeArea_mm2: 2.5; SizeX_mm: 2; SizeY_mm: 1.25; SizeZ_mm: 1.45; EIA_Code: E96; U/M: EA; AEC Category: Q200
R35 = CRCW08052K20JNEA: RES, 2.2 k, 5%, 0.125 W, 0805; Manufacturer: Vishay-Dale; CompType: Resistor; Value: 2.2k; Res_ohm: 2200; Value_Code: 2k20; Tolerance_%: 5; Power_W: 0.125; Value2: 0.125W; VDC_V: 150; TempCo: 200 ppm/C; SizeArea_mm2: 2.5; SizeX_mm: 2; SizeY_mm: 1.25; SizeZ_mm: 1.45; EIA_Code: E24; U/M: EA; AEC Category: Q200
R76 R84 = CRCW08051K00FKEA: RES, 1.00 k, 1%, 0.125 W, 0805; Manufacturer: Vishay-Dale; CompType: Resistor; Value: 1.00k; Res_ohm: 1000; Value_Code: 1k00; Tolerance_%: 1; Power_W: 0.125; Value2: 0.125W; VDC_V: 150; TempCo: 100 ppm/C; SizeArea_mm2: 2.5; SizeX_mm: 2; SizeY_mm: 1.25; SizeZ_mm: 1.45; EIA_Code: E96; U/M: EA; AEC Category: Q200; Green_Lifecycle: Active; Green_REACh: Passed
R77 = CRCW08050000Z0EA: RES, 0, 5%, 0.125 W, 0805; Manufacturer: Vishay-Dale; CompType: Resistor; Value: 0; Value_Code: 0000; Tolerance_%: 5; Power_W: 0.125; Value2: 0.125W; VDC_V: 150; TempCo: 200 ppm/C; SizeArea_mm2: 2.5; SizeX_mm: 2; SizeY_mm: 1.25; SizeZ_mm: 1.45; EIA_Code: E24; U/M: EA; AEC Category: Q200; Green_Lifecycle: Active; Green_REACh: Passed
R78 = CRCW08053K16FKEA: RES, 3.16 k, 1%, 0.125 W, 0805; Manufacturer: Vishay-Dale; CompType: Resistor; Value: 3.16k; Res_ohm: 3160; Value_Code: 3k16; Tolerance_%: 1; Power_W: 0.125; Value2: 0.125W; VDC_V: 150; TempCo: 100 ppm/C; SizeArea_mm2: 2.5; SizeX_mm: 2; SizeY_mm: 1.25; SizeZ_mm: 1.45; EIA_Code: E96; U/M: EA; AEC Category: Q200
R99 = CRCW0805374RFKEA: RES, 374, 1%, 0.125 W, 0805; Manufacturer: Vishay-Dale; CompType: Resistor; Value: 374; Value_Code: 374R; Tolerance_%: 1; Power_W: 0.125; Value2: 0.125W; VDC_V: 150; TempCo: 100 ppm/C; SizeArea_mm2: 2.5; SizeX_mm: 2; SizeY_mm: 1.25; SizeZ_mm: 1.45; EIA_Code: E96; U/M: EA; AEC Category: Q200; Green_Lifecycle: Active; Green_REACh: Passed
R100 = CRCW080537R4FKEA: RES, 37.4, 1%, 0.125 W, 0805; Manufacturer: Vishay-Dale; CompType: Resistor; Value: 37.4; Value_Code: 37R4; Tolerance_%: 1; Power_W: 0.125; Value2: 0.125W; VDC_V: 150; TempCo: 100 ppm/C; SizeArea_mm2: 2.5; SizeX_mm: 2; SizeY_mm: 1.25; SizeZ_mm: 1.45; EIA_Code: E96; U/M: EA; AEC Category: Q200
T1 = CMP-0077115-3: Transformer, 1500 uH, SMT; Manufacturer: Coilcraft; SizeX_mm: 40; SizeZ_mm: 13.9; AEC Qualified: N; Value: 1.5mH; SizeArea_mm2: 1600; AEC Category: Q200; SizeAreaWB_mm2: 1764; Lp: 1500.0; Ns1toNp: 0.083
TP1 TP3 TP4 = 5005: Test Point, Compact, Red, TH; Manufacturer: Keystone; CompType: Test Point Loop; ContactFinish: Silver; Green_Lifecycle: Active; Green_REACh: Passed
TP2 TP6 = 5122: Test Point, Compact, Blue, TH; Manufacturer: Keystone; CompType: Test Point Loop; U/M: EA; ContactFinish: Silver; Green_Lifecycle: Active; Green_REACh: Passed
TP7 TP8 = 5006: Test Point, Compact, Black, TH; Manufacturer: Keystone; CompType: Test Point Loop; ContactFinish: Silver; Green_Lifecycle: Active; Green_REACh: Passed
U1 = CMP-0074855-1: Automotive Catalog BiCMOS Low-Power Current Mode PWM Controller, D0008A (SOIC-8); Alternate Manufacturer: Texas Instruments; SizeAreaWB_mm2: 56.58; U/M: EA; SizeZ_mm: 1.75; SizeX_mm: 4.9; SizeY_mm: 6.2; SizeArea_mm2: 30.38; CompType: IC

## Sheet Hardware.SchDoc: Hardware
size A3; Date: Not shown in title block; ApprovedBy: Not shown in title block; CheckedBy: Not shown in title block; Author: Not shown in title block; CompanyName: Not shown in title block; DrawnBy: X.Gong; Engineer: Not shown in title block; Organization: Not shown in title block; Address1: Not shown in title block; Address2: Not shown in title block; Address3: Not shown in title block; Address4: Not shown in title block; DocumentNumber: 1; Revision: Use project parameter SCH_Rev; SheetNumber: 4; SheetTotal: 4; PageSetup: Record=PageOptions¦CenterHorizontal=True¦CenterVertical=True¦PrintScale=0.69¦XCorrection=1.00¦YCorrection=1.00¦PrintKind=0¦BorderSize=5000000¦LeftOffset=0¦BottomOffset=0¦Orientation=2¦PaperLength=1000¦PaperWidth=1000¦Scale=100¦PaperSource=15¦PrintQuality=600¦MediaType=1¦DitherType=10¦PaperKind=Letter¦PrintScaleMode=1
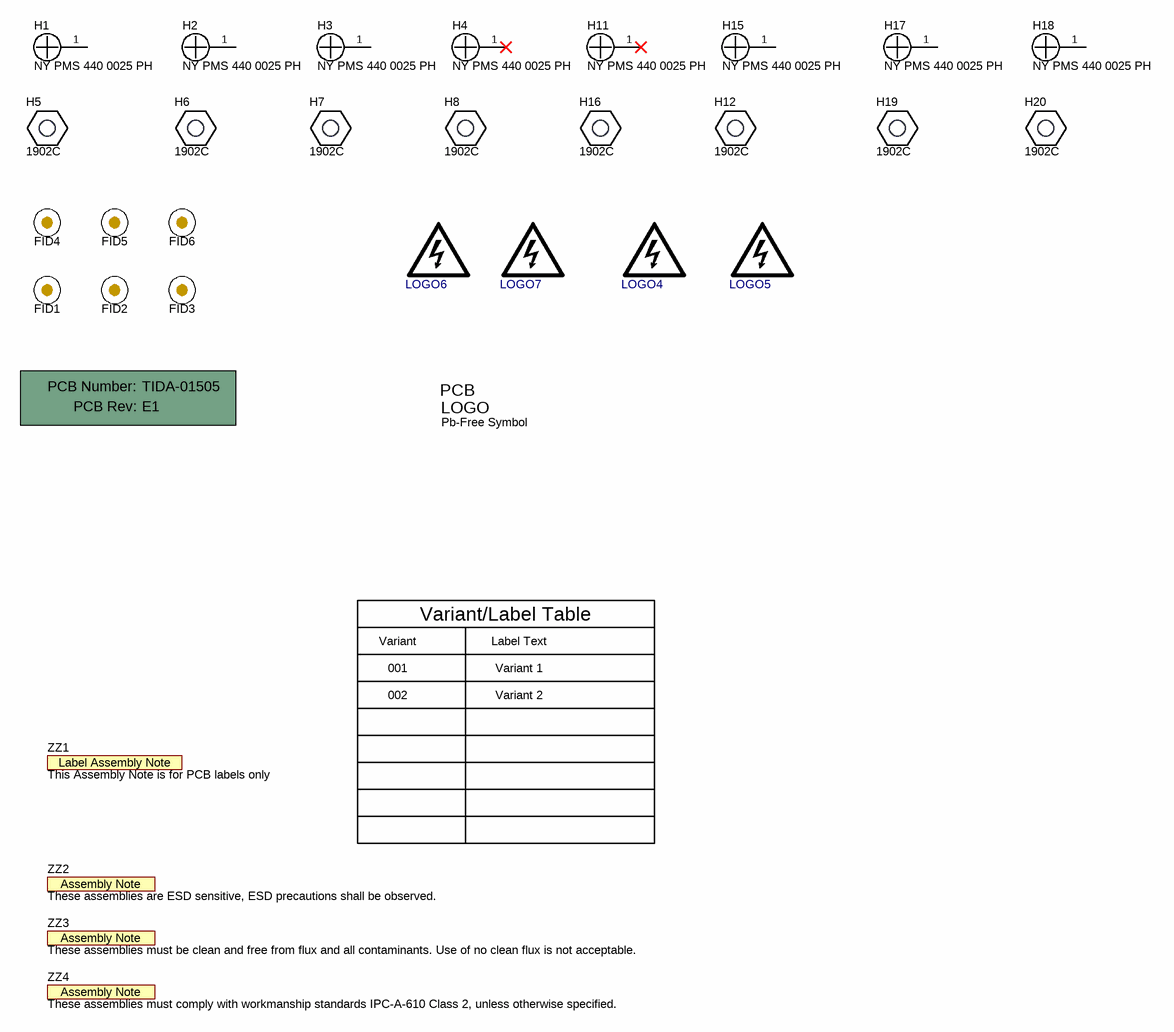
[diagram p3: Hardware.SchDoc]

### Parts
!PCB  Printed Circuit Board  (value not drawn)  (mechanical)
FID1  Fiducial  [Fiducial10-20]  (value not drawn)
FID2  Fiducial  [Fiducial10-20]  (value not drawn)
FID3  Fiducial  [Fiducial10-20]  (value not drawn)
FID4  Fiducial  [Fiducial10-20]  (value not drawn)
FID5  Fiducial  [Fiducial10-20]  (value not drawn)
FID6  Fiducial  [Fiducial10-20]  (value not drawn)
H1  NY PMS 440 0025 PH  [NY PMS 440 0025 PH]
H2  NY PMS 440 0025 PH  [NY PMS 440 0025 PH]
H3  NY PMS 440 0025 PH  [NY PMS 440 0025 PH]
H4  NY PMS 440 0025 PH  [NY PMS 440 0025 PH]
H5  1902C  [Keystone_1902C]
H6  1902C  [Keystone_1902C]
H7  1902C  [Keystone_1902C]
H8  1902C  [Keystone_1902C]
H11  NY PMS 440 0025 PH  [NY PMS 440 0025 PH]
H12  1902C  [Keystone_1902C]
H15  NY PMS 440 0025 PH  [NY PMS 440 0025 PH]
H16  1902C  [Keystone_1902C]
H17  NY PMS 440 0025 PH  [NY PMS 440 0025 PH]
H18  NY PMS 440 0025 PH  [NY PMS 440 0025 PH]
H19  1902C  [Keystone_1902C]
H20  1902C  [Keystone_1902C]
Logo2  Pb-Free Symbol  [Pb-Free_Overlay_Small]  (no BOM)
LOGO4  DANGER HIGH VOLTAGE  [IEC_HighVoltage_Medium]  (value not drawn)  (no BOM)
LOGO5  DANGER HIGH VOLTAGE  [IEC_HighVoltage_Medium]  (value not drawn)  (no BOM)
LOGO6  DANGER HIGH VOLTAGE  [IEC_HighVoltage_Medium]  (value not drawn)  (no BOM)
LOGO7  DANGER HIGH VOLTAGE  [IEC_HighVoltage_Medium]  (value not drawn)  (no BOM)
ZZ1  This Assembly Note is for PCB labels only  [AssemblyNoteLabel]  (no BOM)
ZZ2  These assemblies are ESD sensitive, ESD precautions shall be observed.  [AssemblyNote]  (no BOM)
ZZ3  These assemblies must be clean and free from flux and all contaminants. Use of no clean flux is not acceptable.  [AssemblyNote]  (no BOM)
ZZ4  These assemblies must comply with workmanship standards IPC-A-610 Class 2, unless otherwise specified.  [AssemblyNote]  (no BOM)

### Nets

Not connected (* = marked no-connect by the designer): H1 1; H2 1; H3 1; H4 1*; H11 1*; H15 1; H17 1; H18 1

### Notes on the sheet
- Variant
- Variant/Label Table
- Label Text
- 001
- 002
- Variant 1
- Variant 2

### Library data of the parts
!PCB = PCB: Manufacturer: Any; PartNumber: TIDA-01505; SymbolCreator: a0412235
FID1-FID6 = Fiducial: Fiducial mark.  There is nothing to buy or mount.; SymbolCreator: codlsc
H1-H4 H11 H15 H17 H18 = NY PMS 440 0025 PH: Machine Screw, Round, #4-40 x 1/4, Nylon, Philips panhead; Manufacturer: B&F Fastener Supply; CompType: Hardware; SymbolCreator: codlsc; U/M: EA
H5-H8 H12 H16 H19 H20 = 1902C: Standoff, Hex, 0.5"L #4-40 Nylon; Manufacturer: Keystone; CompType: Hardware
Logo2 = Pb-Free: SymbolCreator: a0412235
LOGO4-LOGO7 = IEC_HighVoltage: IEC 61010-1 High Voltage Warning; SymbolCreator: a0412235
ZZ1 = AssemblyNoteLabel: SymbolCreator: a0412235
ZZ2-ZZ4 = AssemblyNote: SymbolCreator: codlsc

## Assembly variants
001: not fitted C4 C23 C40 C62 C77 FID1 FID2 FID3 R13 R16 R50 R51 R77 R81 R82 R90 R91 R95 R98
